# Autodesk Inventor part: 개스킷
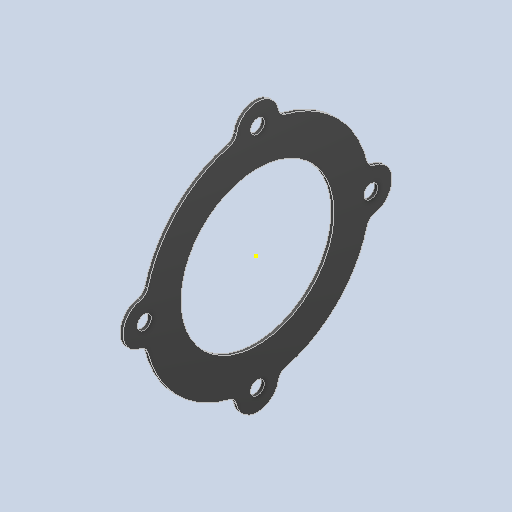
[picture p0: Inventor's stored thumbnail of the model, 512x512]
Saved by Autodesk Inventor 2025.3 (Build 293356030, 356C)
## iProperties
Created: 2025-08
Part Number: 개스킷
Material: 황동, 연질 노란색
Document SubType Name: Modeling
Designer: user
Density: 8.47 g/cm^3
Appearance: 기본값
Sending System: Autodesk Inventor 2026
Preprocessor: ST-DEVELOPER v20.1
Author: jhkim
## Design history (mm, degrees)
sketch "스케치1"
  geometry: 1 further point
  constraints: 1 other
feature "솔리드2"
node "솔리드1"
